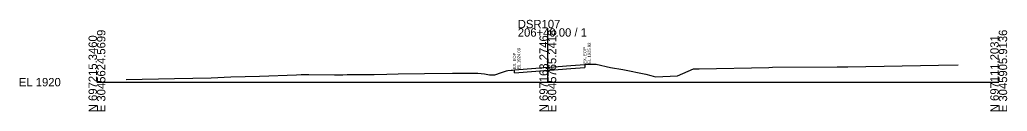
# Model space of a CAD drawing. Extents: x -26 to 19003, y -31 to 24541.
# Drawn here: x 1974.3 to 2302.8, y 11490.3 to 11520.8 of the extents above; entities that cross this region are included whole.
import ezdxf

# ---------------------------------------------------------------- set-up
doc = ezdxf.new("R2010")
doc.units = 0
for name, color, linetype in [('DESIGN - SHEET - Light Grid', 7, 'Continuous'), ('SURVEY - GROUND - Existing Pavement Layer', 7, 'Continuous'), ('SURVEY - GROUND - Existing Pavement Text', 7, 'Continuous'), ('SURVEY - GROUND - Top of Ground', 7, 'Continuous')]:
    doc.layers.add(name, color=color, linetype=linetype)

msp = doc.modelspace()

# ---------------------------------------------------------------- linework, layer by layer
at = {"layer": 'DESIGN - SHEET - Light Grid'}
for p, q in [((2150, 11500), (2150, 11517.95)), ((2000, 11500), (2150, 11500)), ((2150, 11500), (2300, 11500))]:
    msp.add_line(p, q, dxfattribs=at)
at = {"layer": 'SURVEY - GROUND - Existing Pavement Layer'}
for p, q in [((2162.27, 11505.92), (2162.27, 11504.92)), ((2138.86, 11503.09), (2138.86, 11504.09)), ((2138.86, 11503.09), (2145.95, 11503.65)), ((2145.95, 11503.65), (2150, 11503.96)), ((2150, 11503.96), (2150.63, 11504.01)), ((2150.63, 11504.01), (2157.62, 11504.56)), ((2157.62, 11504.56), (2162.27, 11504.92))]:
    msp.add_line(p, q, dxfattribs=at)
at = {"layer": 'SURVEY - GROUND - Top of Ground'}
msp.add_lwpolyline([(2009.68, 11500.88), (2025.83, 11501.2), (2038, 11501.45), (2044.49, 11501.73), (2054.07, 11501.99), (2066.43, 11502.47), (2067.92, 11502.51), (2068.8, 11502.54), (2070.43, 11502.53), (2079.02, 11502.43), (2081.78, 11502.47), (2083.24, 11502.5), (2085.94, 11502.51), (2092.23, 11502.58), (2096.4, 11502.68), (2100.17, 11502.78), (2108.93, 11502.83), (2118.28, 11502.97), (2118.99, 11502.96), (2126.66, 11503.02), (2128.92, 11502.78), (2130.61, 11502.45), (2131.6, 11502.46), (2132.31, 11502.49), (2134.58, 11503.21), (2136.3, 11503.81), (2136.73, 11503.86), (2137.76, 11503.96), (2138.29, 11504.03), (2138.86, 11504.09), (2145.95, 11504.65), (2150, 11504.96), (2150.63, 11505.01), (2157.62, 11505.56), (2162.27, 11505.92), (2162.67, 11505.95), (2163.4, 11505.98), (2164.46, 11505.95), (2166.13, 11505.94), (2170.87, 11504.92), (2174.93, 11504.17), (2182.59, 11502.71), (2184.27, 11502.25), (2185.81, 11501.82), (2193.14, 11502.12), (2198.48, 11504.41), (2200.38, 11504.44), (2223.47, 11504.93), (2224.79, 11504.94), (2246.22, 11505.09), (2249.81, 11505.08), (2279.97, 11505.64), (2286.5, 11505.79)], dxfattribs=at)

# ---------------------------------------------------------------- texts
at = {"layer": 'DESIGN - SHEET - Light Grid'}
for s, p in [('DSR107', (2140, 11517.95)), ('206+40.00 / 1', (2140, 11515.15)), ('EL 1920', (1974, 11498.6))]:
    msp.add_text(s, height=2.8, dxfattribs=at).set_placement(p)
for s, p in [('N 697215.3460', (2000, 11490)), ('E 3045624.5699', (2002.8, 11490)), ('N 697163.2746', (2150, 11490)), ('E 3045765.2418', (2152.8, 11490)), ('N 697111.2031', (2300, 11490)), ('E 3045905.9136', (2302.8, 11490))]:
    msp.add_text(s, height=2.8, rotation=90, dxfattribs=at).set_placement(p)
at = {"layer": 'SURVEY - GROUND - Existing Pavement Text'}
for s, p in [('EL.1925.92', (2164.27, 11506.12)), ('EX. EOP', (2139.36, 11504.29)), ('EL.1924.09', (2140.86, 11504.29)), ('EX. EOP', (2162.77, 11506.12))]:
    msp.add_text(s, height=1, rotation=90, dxfattribs=at).set_placement(p)

doc.saveas('drawing.dxf')
